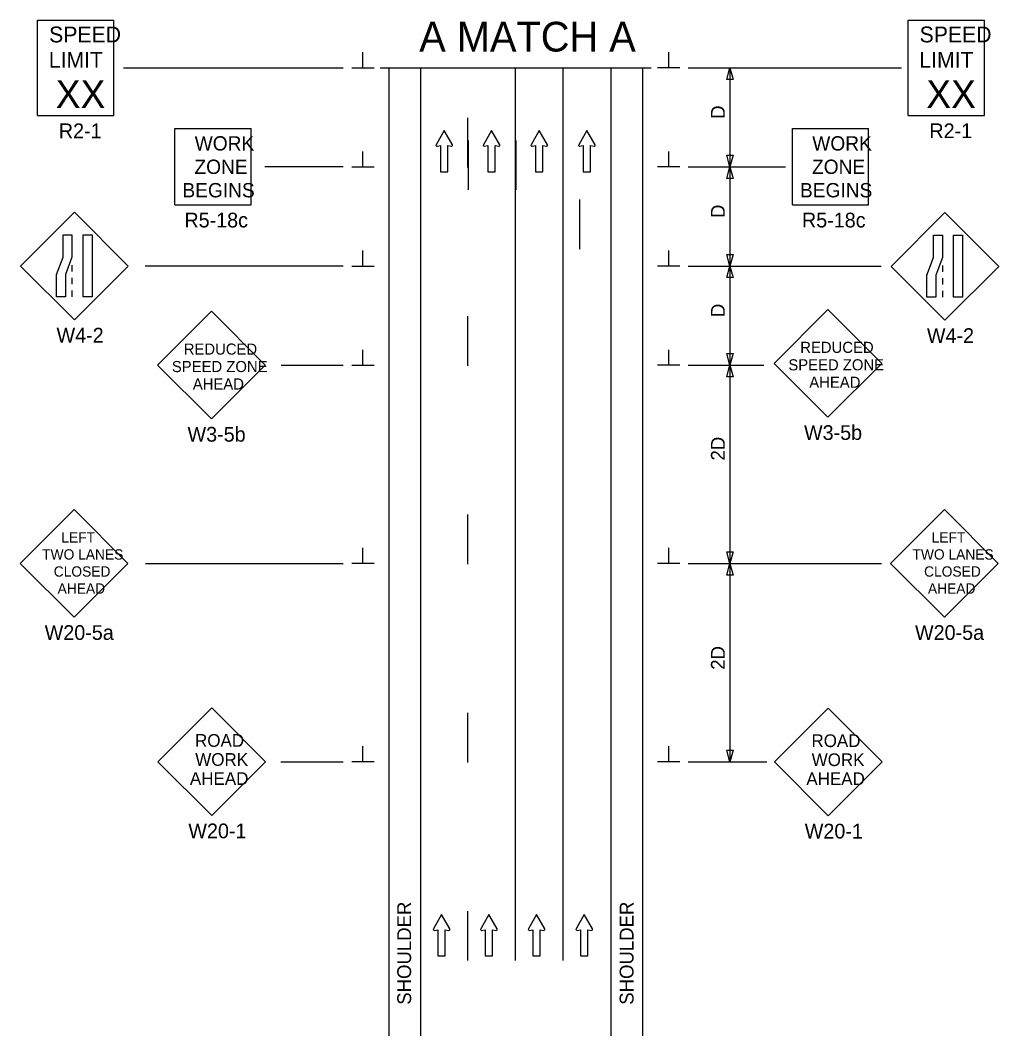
# Model space of a CAD drawing. Extents: x 16512 to 19512, y 5761 to 6974.
# Drawn here: x 17851 to 18345, y 6401 to 6913 of the extents above; entities that cross this region are included whole.
import ezdxf

# ---------------------------------------------------------------- set-up
doc = ezdxf.new("R2010")
doc.units = 0
for name, color, linetype in [('ALI_LEGAL_EX', 7, 'Continuous'), ('MT_SCRATCH_LEVEL_E', 7, 'Continuous'), ('PAVT_EDGE_EX', 7, 'Continuous'), ('TRAFFIC_SIGNS_PR', 7, 'Continuous'), ('TYPICAL_TEXT_DIMEN_PR', 7, 'Continuous')]:
    doc.layers.add(name, color=color, linetype=linetype)

msp = doc.modelspace()

# ---------------------------------------------------------------- linework, layer by layer
at = {"layer": 'ALI_LEGAL_EX'}
for p, q in [((18101.18, 6438.7), (18101.18, 6889.05)), ((18125.18, 6438.7), (18125.18, 6889.05))]:
    msp.add_line(p, q, dxfattribs=at)
for points in [[(18077.18, 6838.7), (18077.18, 6863.7)], [(18101.18, 6838.7), (18101.18, 6863.7)], [(18125.18, 6838.7), (18125.18, 6863.7)], [(18077.28, 6852.4), (18077.28, 6827.4)], [(18101.28, 6852.4), (18101.28, 6827.4)], [(18133.42, 6822.52), (18133.42, 6797.52)], [(18077.18, 6738.7), (18077.18, 6763.7)], [(18101.18, 6738.7), (18101.18, 6763.7)], [(18125.18, 6738.7), (18125.18, 6763.7)], [(18077.18, 6638.7), (18077.18, 6663.7)], [(18101.18, 6638.7), (18101.18, 6663.7)], [(18125.18, 6638.7), (18125.18, 6663.7)], [(18077.18, 6538.7), (18077.18, 6563.7)], [(18101.18, 6538.7), (18101.18, 6563.7)], [(18125.18, 6538.7), (18125.18, 6563.7)], [(18077.18, 6438.7), (18077.18, 6463.7)], [(18101.18, 6438.7), (18101.18, 6463.7)], [(18125.18, 6438.7), (18125.18, 6463.7)]]:
    msp.add_lwpolyline(points, dxfattribs=at)
at = {"layer": 'MT_SCRATCH_LEVEL_E'}
for p, q in [((18065.19, 6857.36), (18061.08, 6850.12)), ((18069.34, 6850.12), (18065.19, 6857.36)), ((18089.05, 6857.36), (18084.94, 6850.12)), ((18093.19, 6850.12), (18089.05, 6857.36)), ((18113.1, 6857.36), (18108.99, 6850.12)), ((18117.25, 6850.12), (18113.1, 6857.36)), ((18137.15, 6857.36), (18133.04, 6850.12)), ((18137.15, 6857.36), (18133.04, 6850.12)), ((18141.3, 6850.12), (18137.15, 6857.36)), ((18141.3, 6850.12), (18137.15, 6857.36)), ((18061.57, 6849.44), (18063.34, 6849.75)), ((18063.34, 6849.75), (18063.34, 6836.5)), ((18067.08, 6836.5), (18067.08, 6849.75)), ((18067.08, 6849.75), (18068.86, 6849.44)), ((18085.42, 6849.44), (18087.19, 6849.75)), ((18087.19, 6849.75), (18087.19, 6836.5)), ((18090.94, 6836.5), (18090.94, 6849.75)), ((18090.94, 6849.75), (18092.71, 6849.44)), ((18109.47, 6849.44), (18111.25, 6849.75)), ((18111.25, 6849.75), (18111.25, 6836.5)), ((18114.99, 6836.5), (18114.99, 6849.75)), ((18114.99, 6849.75), (18116.77, 6849.44)), ((18133.52, 6849.44), (18135.3, 6849.76)), ((18133.52, 6849.44), (18135.3, 6849.76)), ((18135.3, 6849.76), (18135.3, 6836.5)), ((18135.3, 6849.76), (18135.3, 6836.5)), ((18139.04, 6836.5), (18139.04, 6849.76)), ((18139.04, 6849.76), (18140.82, 6849.44)), ((18139.04, 6836.5), (18139.04, 6849.76)), ((18139.04, 6849.76), (18140.82, 6849.44)), ((18063.34, 6836.5), (18067.08, 6836.5)), ((18087.19, 6836.5), (18090.94, 6836.5)), ((18111.25, 6836.5), (18114.99, 6836.5)), ((18135.3, 6836.5), (18139.04, 6836.5)), ((18135.3, 6836.5), (18139.04, 6836.5)), ((18063.86, 6461.9), (18059.75, 6454.66)), ((18068, 6454.66), (18063.86, 6461.9)), ((18087.71, 6461.9), (18083.6, 6454.66)), ((18091.86, 6454.66), (18087.71, 6461.9)), ((18111.76, 6461.9), (18107.65, 6454.66)), ((18115.91, 6454.66), (18111.76, 6461.9)), ((18135.81, 6461.9), (18131.7, 6454.66)), ((18135.81, 6461.9), (18131.7, 6454.66)), ((18139.96, 6454.66), (18135.81, 6461.9)), ((18139.96, 6454.66), (18135.81, 6461.9)), ((18060.23, 6453.98), (18062.01, 6454.29)), ((18062.01, 6454.29), (18062.01, 6441.04)), ((18065.75, 6441.04), (18065.75, 6454.29)), ((18065.75, 6454.29), (18067.52, 6453.98)), ((18084.08, 6453.98), (18085.86, 6454.29)), ((18085.86, 6454.29), (18085.86, 6441.04)), ((18089.6, 6441.04), (18089.6, 6454.29)), ((18089.6, 6454.29), (18091.38, 6453.98)), ((18108.13, 6453.98), (18109.91, 6454.29)), ((18109.91, 6454.29), (18109.91, 6441.04)), ((18113.65, 6441.04), (18113.65, 6454.29)), ((18113.65, 6454.29), (18115.43, 6453.98)), ((18132.19, 6453.98), (18133.96, 6454.29)), ((18132.19, 6453.98), (18133.96, 6454.29)), ((18133.96, 6454.29), (18133.96, 6441.04)), ((18133.96, 6454.29), (18133.96, 6441.04)), ((18137.7, 6441.04), (18137.7, 6454.29)), ((18137.7, 6454.29), (18139.48, 6453.98)), ((18137.7, 6441.04), (18137.7, 6454.29)), ((18137.7, 6454.29), (18139.48, 6453.98)), ((18062.01, 6441.04), (18065.75, 6441.04)), ((18085.86, 6441.04), (18089.6, 6441.04)), ((18109.91, 6441.04), (18113.65, 6441.04)), ((18133.96, 6441.04), (18137.7, 6441.04)), ((18133.96, 6441.04), (18137.7, 6441.04))]:
    msp.add_line(p, q, dxfattribs=at)
for centre, start, end in [((18061.49, 6849.9), 150.4248, 279.9638), ((18068.93, 6849.9), 260.0362, 29.7731), ((18085.34, 6849.9), 150.4248, 279.9638), ((18092.78, 6849.9), 260.0362, 29.7731), ((18109.4, 6849.9), 150.4248, 279.9638), ((18116.84, 6849.9), 260.0362, 29.7731), ((18133.45, 6849.9), 150.4248, 279.9638), ((18133.45, 6849.9), 150.4248, 279.9638), ((18140.89, 6849.9), 260.0362, 29.7731), ((18140.89, 6849.9), 260.0362, 29.7731), ((18060.15, 6454.44), 150.4248, 279.9638), ((18067.6, 6454.44), 260.0362, 29.7731), ((18084.01, 6454.44), 150.4248, 279.9638), ((18091.45, 6454.44), 260.0362, 29.7731), ((18108.06, 6454.44), 150.4248, 279.9638), ((18115.5, 6454.44), 260.0362, 29.7731), ((18132.11, 6454.44), 150.4248, 279.9638), ((18132.11, 6454.44), 150.4248, 279.9638), ((18139.55, 6454.44), 260.0362, 29.7731), ((18139.55, 6454.44), 260.0362, 29.7731)]:
    msp.add_arc(centre, 0.463, start, end, dxfattribs=at)
at = {"layer": 'PAVT_EDGE_EX'}
for p, q in [((18037.18, 6889.05), (18037.18, 6400.84)), ((18053.18, 6889.05), (18053.18, 6400.84)), ((18149.18, 6889.05), (18149.18, 6400.84)), ((18165.18, 6889.05), (18165.18, 6400.84))]:
    msp.add_line(p, q, dxfattribs=at)
at = {"layer": 'TRAFFIC_SIGNS_PR'}
for p, q in [((17860.15, 6912.96), (17898.55, 6912.96)), ((17860.15, 6864.96), (17860.15, 6912.96)), ((17898.55, 6864.96), (17898.55, 6912.96)), ((18299.21, 6912.97), (18337.61, 6912.97)), ((18299.21, 6864.97), (18299.21, 6912.97)), ((18337.61, 6864.97), (18337.61, 6912.97)), ((17860.15, 6864.96), (17898.55, 6864.96)), ((18299.21, 6864.97), (18337.61, 6864.97)), ((17929.35, 6819.94), (17929.35, 6858.34)), ((17929.35, 6858.34), (17967.75, 6858.34)), ((17967.75, 6819.94), (17967.75, 6858.34)), ((18240.82, 6819.94), (18240.82, 6858.34)), ((18240.82, 6858.34), (18279.22, 6858.34)), ((18279.22, 6819.94), (18279.22, 6858.34)), ((17929.35, 6819.94), (17967.75, 6819.94)), ((18240.82, 6819.94), (18279.22, 6819.94)), ((17878.71, 6816.17), (17851.56, 6789.02)), ((17905.86, 6789.02), (17878.71, 6816.17)), ((18317.69, 6815.98), (18290.53, 6788.83)), ((18344.84, 6788.83), (18317.69, 6815.98)), ((17851.56, 6789.02), (17878.71, 6761.87)), ((17877.46, 6789.51), (17877.46, 6786.31)), ((17878.71, 6761.87), (17905.86, 6789.02)), ((18290.53, 6788.83), (18317.69, 6761.68)), ((18316.44, 6789.32), (18316.44, 6786.12)), ((18317.69, 6761.68), (18344.84, 6788.83)), ((17877.46, 6783.11), (17877.46, 6779.91)), ((18316.44, 6782.92), (18316.44, 6779.72)), ((17877.46, 6776.71), (17877.46, 6773.51)), ((18316.44, 6776.52), (18316.44, 6773.32)), ((17947.78, 6766.19), (17920.62, 6739.04)), ((17974.93, 6739.04), (17947.78, 6766.19)), ((18258.7, 6767.07), (18231.54, 6739.91)), ((18285.85, 6739.91), (18258.7, 6767.07)), ((18231.54, 6739.91), (18258.7, 6712.76)), ((18258.7, 6712.76), (18285.85, 6739.91)), ((17920.62, 6739.04), (17947.78, 6711.89)), ((17947.78, 6711.89), (17974.93, 6739.04)), ((17878.55, 6666.2), (17851.4, 6639.05)), ((17905.7, 6639.05), (17878.55, 6666.2)), ((18317.5, 6666.2), (18290.34, 6639.05)), ((18344.65, 6639.05), (18317.5, 6666.2)), ((17851.4, 6639.05), (17878.55, 6611.9)), ((17878.55, 6611.9), (17905.7, 6639.05)), ((18290.34, 6639.05), (18317.5, 6611.9)), ((18317.5, 6611.9), (18344.65, 6639.05)), ((17947.98, 6566.17), (17920.83, 6539.01)), ((17975.14, 6539.01), (17947.98, 6566.17)), ((18258.87, 6566.05), (18231.72, 6538.89)), ((18286.02, 6538.89), (18258.87, 6566.05)), ((17920.83, 6539.01), (17947.98, 6511.86)), ((17947.98, 6511.86), (17975.14, 6539.01)), ((18231.72, 6538.89), (18258.87, 6511.74)), ((18258.87, 6511.74), (18286.02, 6538.89))]:
    msp.add_line(p, q, dxfattribs=at)
for points in [[(17877.46, 6804.76), (17877.46, 6793.58), (17874.12, 6784.69), (17874.12, 6773.51), (17869.63, 6773.51), (17869.63, 6784.69), (17872.97, 6793.58), (17872.97, 6804.76)], [(17887.6, 6804.76), (17887.6, 6773.51), (17883.11, 6773.51), (17883.11, 6804.76)], [(18316.44, 6804.57), (18316.44, 6793.38), (18313.1, 6784.5), (18313.1, 6773.32), (18308.6, 6773.32), (18308.6, 6784.5), (18311.95, 6793.38), (18311.95, 6804.57)], [(18326.58, 6804.57), (18326.58, 6773.32), (18322.08, 6773.32), (18322.08, 6804.57)]]:
    msp.add_lwpolyline(points, close=True, dxfattribs=at)
at = {"layer": 'TYPICAL_TEXT_DIMEN_PR'}
for p, q in [((18024.15, 6889.05), (18024.15, 6896.83)), ((18178.4, 6889.05), (18178.4, 6896.83)), ((17903.45, 6889.05), (18014.28, 6889.05)), ((18018.53, 6889.05), (18029.78, 6889.05)), ((18032.85, 6889.05), (18169.5, 6889.05)), ((18184.03, 6889.05), (18172.78, 6889.05)), ((18188.28, 6889.05), (18295.87, 6889.05)), ((18207.71, 6883.19), (18209.28, 6889.05)), ((18209.28, 6889.05), (18209.28, 6839.05)), ((18209.28, 6889.05), (18210.85, 6883.19)), ((18209.28, 6883.19), (18207.71, 6883.19)), ((18210.85, 6883.19), (18209.28, 6883.19)), ((18024.15, 6839.05), (18024.15, 6846.83)), ((18178.4, 6839.05), (18178.4, 6846.83)), ((18209.28, 6839.05), (18207.71, 6844.91)), ((18207.71, 6844.91), (18209.28, 6844.91)), ((18209.28, 6844.91), (18210.85, 6844.91)), ((18210.85, 6844.91), (18209.28, 6839.05)), ((18014.28, 6839.05), (17974.74, 6839.05)), ((18018.53, 6839.05), (18029.78, 6839.05)), ((18184.03, 6839.05), (18172.78, 6839.05)), ((18188.28, 6839.05), (18237.37, 6839.05)), ((18207.71, 6833.19), (18209.28, 6839.05)), ((18209.28, 6839.05), (18210.85, 6833.19)), ((18209.28, 6839.05), (18209.28, 6789.05)), ((18209.28, 6833.19), (18207.71, 6833.19)), ((18210.85, 6833.19), (18209.28, 6833.19)), ((18024.15, 6789.05), (18024.15, 6796.83)), ((18178.4, 6789.05), (18178.4, 6796.83)), ((18209.28, 6789.05), (18207.71, 6794.91)), ((18207.71, 6794.91), (18209.28, 6794.91)), ((18209.28, 6794.91), (18210.85, 6794.91)), ((18210.85, 6794.91), (18209.28, 6789.05)), ((18014.28, 6789.05), (17914.42, 6789.05)), ((18018.53, 6789.05), (18029.78, 6789.05)), ((18184.03, 6789.05), (18172.78, 6789.05)), ((18188.28, 6789.05), (18285.55, 6789.05)), ((18207.71, 6783.19), (18209.28, 6789.05)), ((18209.28, 6789.05), (18209.28, 6739.05)), ((18209.28, 6789.05), (18210.85, 6783.19)), ((18209.28, 6783.19), (18207.71, 6783.19)), ((18210.85, 6783.19), (18209.28, 6783.19)), ((18024.15, 6739.05), (18024.15, 6746.83)), ((18178.4, 6739.05), (18178.4, 6746.83)), ((18209.28, 6739.05), (18207.71, 6744.91)), ((18207.71, 6744.91), (18209.28, 6744.91)), ((18209.28, 6744.91), (18210.85, 6744.91)), ((18210.85, 6744.91), (18209.28, 6739.05)), ((17982.91, 6739.05), (18014.28, 6739.05)), ((18018.53, 6739.05), (18029.78, 6739.05)), ((18184.03, 6739.05), (18172.78, 6739.05)), ((18188.28, 6739.05), (18226.47, 6739.05)), ((18207.71, 6733.19), (18209.28, 6739.05)), ((18207.71, 6733.19), (18209.28, 6739.05)), ((18209.28, 6739.05), (18209.28, 6639.05)), ((18209.28, 6739.05), (18210.85, 6733.19)), ((18209.28, 6739.05), (18210.85, 6733.19)), ((18209.28, 6739.05), (18209.28, 6639.05)), ((18209.28, 6733.19), (18207.71, 6733.19)), ((18209.28, 6733.19), (18207.71, 6733.19)), ((18210.85, 6733.19), (18209.28, 6733.19)), ((18210.85, 6733.19), (18209.28, 6733.19)), ((18024.15, 6639.05), (18024.15, 6646.83)), ((18024.15, 6639.05), (18024.15, 6646.83)), ((18178.4, 6639.05), (18178.4, 6646.83)), ((18178.4, 6639.05), (18178.4, 6646.83)), ((18209.28, 6639.05), (18207.71, 6644.91)), ((18207.71, 6644.91), (18209.28, 6644.91)), ((18209.28, 6644.91), (18210.85, 6644.91)), ((18210.85, 6644.91), (18209.28, 6639.05)), ((17914.48, 6639.05), (18014.28, 6639.05)), ((18029.78, 6639.05), (18018.53, 6639.05)), ((18029.78, 6639.05), (18018.53, 6639.05)), ((18184.03, 6639.05), (18172.78, 6639.05)), ((18184.03, 6639.05), (18172.78, 6639.05)), ((18188.28, 6639.05), (18285.66, 6639.05)), ((18188.28, 6639.05), (18214.28, 6639.05)), ((18207.71, 6633.19), (18209.28, 6639.05)), ((18209.28, 6639.05), (18209.28, 6539.05)), ((18209.28, 6639.05), (18210.85, 6633.19)), ((18209.28, 6633.19), (18207.71, 6633.19)), ((18210.85, 6633.19), (18209.28, 6633.19)), ((18024.15, 6539.05), (18024.15, 6546.83)), ((18178.4, 6539.05), (18178.4, 6546.83)), ((18209.28, 6539.05), (18207.71, 6544.91)), ((18207.71, 6544.91), (18209.28, 6544.91)), ((18209.28, 6544.91), (18210.85, 6544.91)), ((18210.85, 6544.91), (18209.28, 6539.05)), ((17982.71, 6539.05), (18014.28, 6539.05)), ((18029.78, 6539.05), (18018.53, 6539.05)), ((18184.03, 6539.05), (18172.78, 6539.05)), ((18188.28, 6539.05), (18227.91, 6539.05))]:
    msp.add_line(p, q, dxfattribs=at)

# ---------------------------------------------------------------- texts
at = {"layer": 'TRAFFIC_SIGNS_PR'}
for s, height, p in [('SPEED', 8, (17865.92, 6901.82)), ('SPEED', 8, (18304.97, 6901.83)), ('LIMIT', 8, (17865.75, 6889.02)), ('LIMIT', 8, (18304.81, 6889.03)), ('XX', 14.031, (17869.26, 6868.72)), ('XX', 14.031, (18308.32, 6868.73)), ('R2-1', 7.44, (17870.83, 6853.52)), ('R2-1', 7.44, (18309.88, 6853.53)), ('WORK', 7.217, (17939.35, 6847.3)), ('WORK', 7.217, (18250.82, 6847.3)), ('ZONE', 7.217, (17939.23, 6835.49)), ('ZONE', 7.217, (18250.7, 6835.49)), ('BEGINS', 7.217, (17933.16, 6823.68)), ('BEGINS', 7.217, (18244.63, 6823.68)), ('R5-18c', 7.44, (17934.16, 6808.5)), ('R5-18c', 7.44, (18245.63, 6808.5)), ('W4-2', 7.44, (17869.67, 6750.43)), ('W4-2', 7.44, (18308.64, 6750.24)), ('REDUCED', 5.6, (17933.83, 6744.35)), ('REDUCED', 5.6, (18244.75, 6745.22)), ('SPEED ZONE', 5.6, (17927.83, 6735.55)), ('SPEED ZONE', 5.6, (18238.75, 6736.42)), ('AHEAD', 5.6, (17938.39, 6726.75)), ('AHEAD', 5.6, (18249.31, 6727.62)), ('W3-5b', 7.44, (18246.65, 6701.32)), ('W3-5b', 7.44, (17935.73, 6700.45)), ('LEFT', 5.2, (17872.09, 6649.58)), ('LEFT', 5.2, (18311.03, 6649.58)), ('TWO LANES', 5.2, (17862.41, 6640.98)), ('TWO LANES', 5.2, (18301.36, 6640.98)), ('CLOSED', 5.2, (17868.26, 6632.38)), ('CLOSED', 5.2, (18307.21, 6632.38)), ('AHEAD', 5.2, (17870.21, 6623.78)), ('AHEAD', 5.2, (18309.16, 6623.78)), ('W20-5a', 7.44, (17863.69, 6600.46)), ('W20-5a', 7.44, (18302.64, 6600.46)), ('ROAD', 6.4, (17939.53, 6546.55)), ('ROAD', 6.4, (18250.41, 6546.43)), ('WORK', 6.4, (17939.63, 6536.95)), ('WORK', 6.4, (18250.52, 6536.83)), ('AHEAD', 6.4, (17936.94, 6527.35)), ('AHEAD', 6.4, (18247.83, 6527.23)), ('W20-1', 7.44, (17936.15, 6500.42)), ('W20-1', 7.44, (18247.04, 6500.3))]:
    msp.add_text(s, height=height, dxfattribs=at).set_placement(p)
at = {"layer": 'TYPICAL_TEXT_DIMEN_PR'}
msp.add_text('A MATCH A', height=15, dxfattribs=at).set_placement((18052.6, 6897.23))
for s, p in [('D', (18206.72, 6863.27)), ('D', (18206.72, 6813.27)), ('D', (18206.72, 6763.27)), ('2D', (18206.72, 6690.94)), ('2D', (18206.72, 6585.41)), ('SHOULDER', (18048.51, 6416.45)), ('SHOULDER', (18160.68, 6416.45))]:
    msp.add_text(s, height=7, rotation=90, dxfattribs=at).set_placement(p)

doc.saveas('drawing.dxf')
